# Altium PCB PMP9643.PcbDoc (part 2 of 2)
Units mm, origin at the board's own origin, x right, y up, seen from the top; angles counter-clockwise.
Board outline 136 x 91.5 mm, 2 copper layers (Top Layer, Bottom Layer), stack 1.575 mm thick; 90 components, 34 nets, 184 pads, 0 vias.
Unrouted connection lines stored in the file: 5.
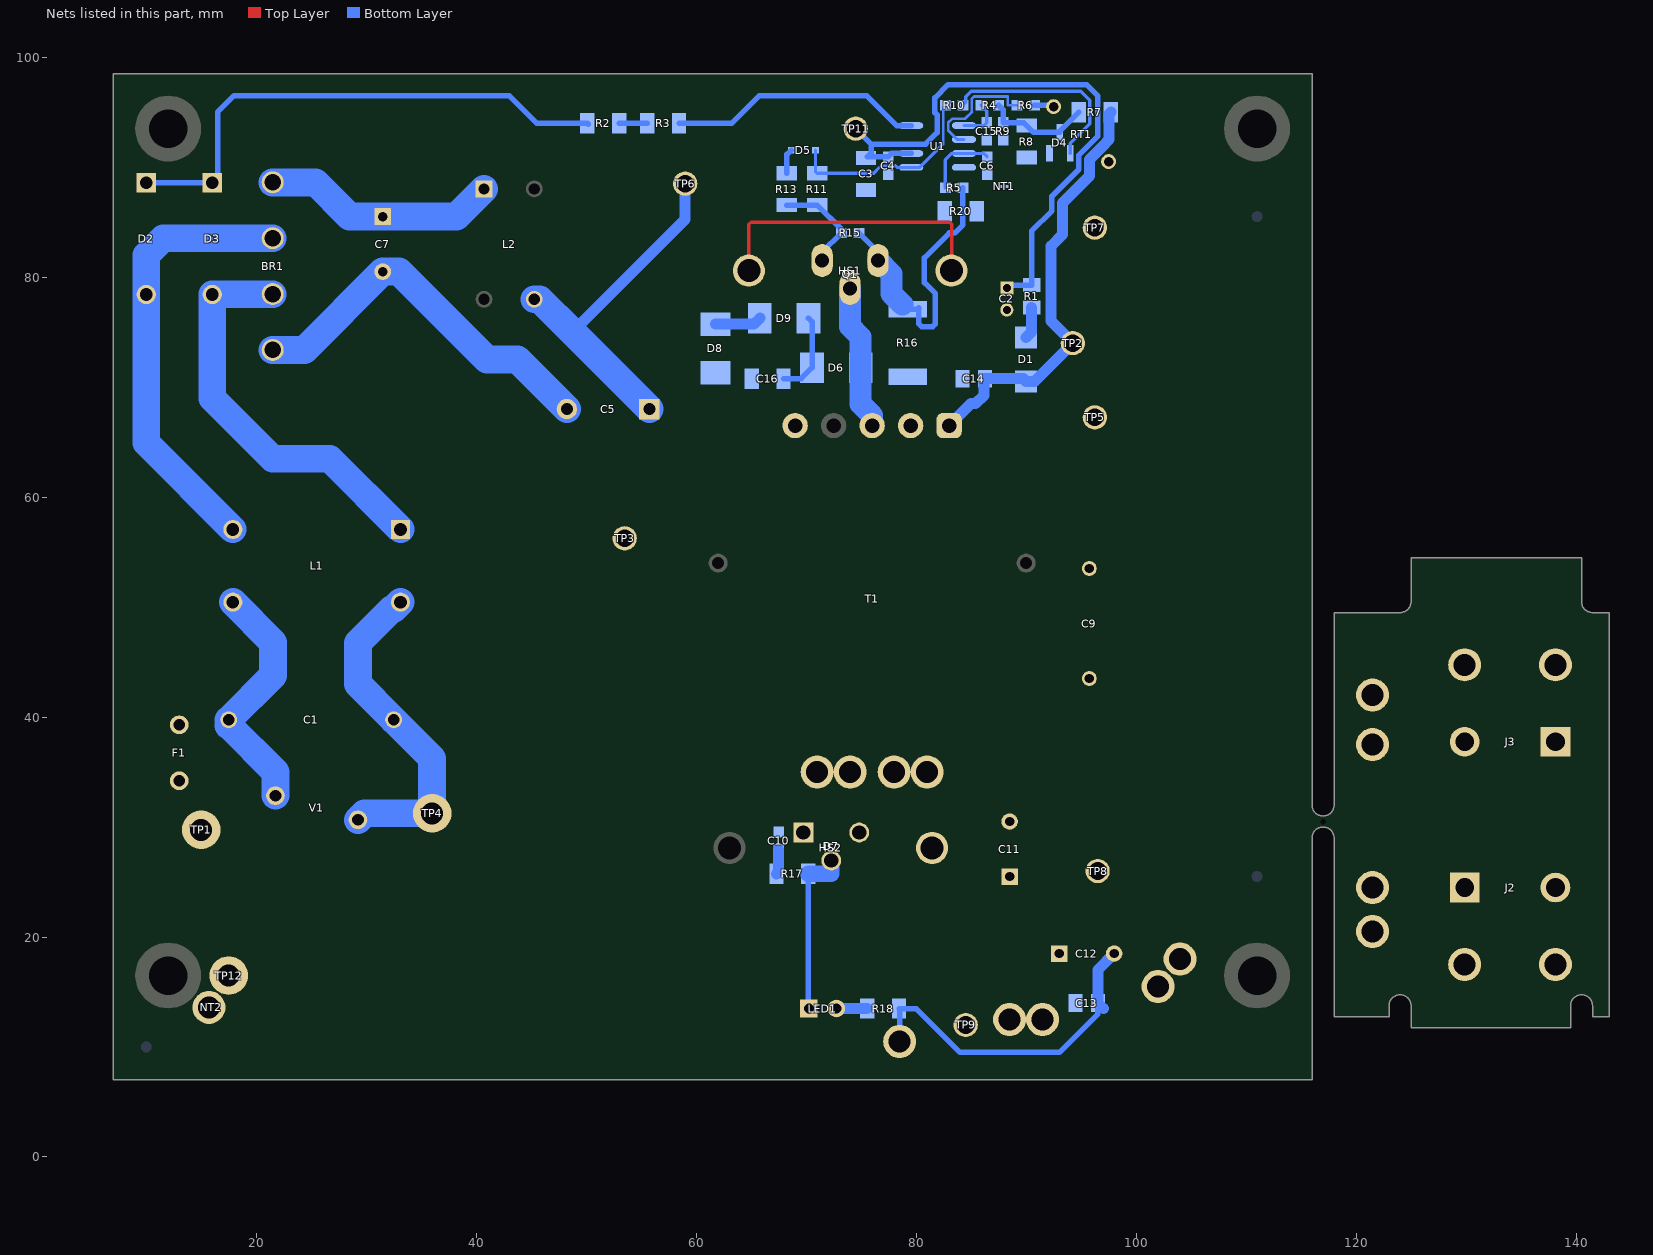
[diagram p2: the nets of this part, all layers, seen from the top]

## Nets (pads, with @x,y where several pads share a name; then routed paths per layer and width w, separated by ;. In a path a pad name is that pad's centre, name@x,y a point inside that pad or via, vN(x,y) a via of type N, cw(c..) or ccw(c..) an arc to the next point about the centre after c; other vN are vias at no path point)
+VOUT: C11.1 C12.1 C13.2 D7.2 HS2.2 J3.1 J3.2 LED1.1 pad.0@88.5,12.5 pad.0@91.5,12.5 pad.0@121.5,37.5 pad.0@121.5,42 pad.0@129.872,44.75 pad.0@138.127,44.75 R17.1 TP9.1 | length 15.6
  Bottom Layer w0.5: R17.1@70.2,25.75 70.2,13.55 LED1.1@70.25,13.5
  Bottom Layer w1.5: R17.1@70.2,25.75 72.29,25.75 D7.2@72.29,26.96
+VSW: D6.2 Q1.2 T1.3 | length 13.3
  Bottom Layer w2: Q1.2@74,78.97 74,75.5 74.96,74.54 D6.2@74.96,71.76 74.96,68.46 76,67.42 T1.3@76,66.5
-VPRI: BR1.4 C2.2 C5.2 C7.2 C9.2 C14.2 HS1.1 HS1.2 NT1.2 R16.1 RT1.1 T1.2 TP3.1 TP5.1 TP7.1 | length 62
  Top Layer w0.3: HS1.1@64.793,80.588 64.793,84.793 65,85 83.075,85 83.25,84.825 83.25,80.631 HS1.2@83.208,80.588
  Bottom Layer w2.54: BR1.4@21.5,73.38 24.38,73.38 C7.2@31.5,80.5 33,80.5 41,72.5 43.75,72.5 C5.2@48.25,68
ACA: BR1.2 D2.2 L1.2 | length 40.3
  Bottom Layer w2.5: L1.2@17.88,57.052 10,64.932 D2.2@10,78.42 10,82 11.54,83.54 BR1.2@21.5,83.54
ACB: BR1.3 D3.2 L1.1 | length 37
  Bottom Layer w2.5: BR1.3@21.5,78.46 21.46,78.42 D3.2@16,78.42 16,69 21.5,63.5 26.672,63.5 L1.1@33.12,57.052
CS: Q1.3 R5.1 R15.1 R16.2 | length 27.6
  Bottom Layer w0.5: R15.1@74.8,84.01 76.54,82.27 Q1.3@76.54,81.51 ; R16.2@78.75,77.5 78.81,77.5 R16.2@79.25,77.06 80.075,77.06 80.25,77.235 80.25,75.75 80.5,75.5 81.5,75.5 81.75,75.75 81.75,78.5 80.75,79.5 80.75,81.75 83.017,84.017 83.525,84.017 84.25,84.742 R5.1@84.25,88.125
  Bottom Layer w2: Q1.3@76.54,81.51 77.75,80.3 77.75,78.5 R16.2@78.75,77.5
DRV: D5.1 R10.2 R11.2 U1.5 | length 19.5
  Bottom Layer w0.2: 76.625,89.93 76.656,89.93 76.851,90.125 78.12,90.125 ; 82.45,94.375 82.45,95.425 82.475,95.45 R10.2@82.65,95.625
  Bottom Layer w0.25: 82.25,91.901 82.475,92.126 R10.2@82.475,95.45
  Bottom Layer w0.3: D5.1@70.85,91.55 70.85,89.6 R11.2@71,89.45 76.145,89.45 76.625,89.93 ; 78.12,90.125 78.275,89.97 U1.5@79.55,89.97 80.319,89.97 82.25,91.901
EARTH: NT2.1 pad.0@15.7,13.6 TP12.1
MAG: C14.1 D1.2 R7.1 T1.1 TP2.1 | length 39.5
  Bottom Layer w1: T1.1@83,66.5 85,68.5 85.41,68.5 86.16,69.25 86.16,70.654 C14.1@86.266,70.76 89.75,70.76 D1.2@90,70.51 90.76,70.51 TP2.1@94.25,74 92.25,76 92.25,82.806 93.3,83.856 93.3,86.75 95.755,89.205 95.755,90.7 96.93,91.875 97.55,92.495 97.55,94.85 R7.1@97.7,95
NetBR1_1: BR1.1 C7.1 L2.1 | length 21.5
  Bottom Layer w2.54: BR1.1@21.5,88.62 25.38,88.62 28.5,85.5 C7.1@31.5,85.5 38.198,85.5 L2.1@40.714,88.017
NetC1_1: C1.1 L1.4 TP4.1 V1.2 | length 30.7
  Bottom Layer w2.54: V1.2@29.25,30.65 29.85,31.25 TP4.1@36,31.25 36,36.25 C1.1@32.5,39.75 29.25,43 29.25,46.75 32.328,49.828 32.5,49.828 L1.4@33.12,50.448
NetC1_2: C1.2 F1.1 L1.3 V1.1 | length 22
  Bottom Layer w2.54: C1.2@17.5,39.25 21.75,35 V1.1@21.75,32.85 ; C1.2@17.5,39.75 21.539,43.789 21.539,46.789 L1.3@17.88,50.448
NetC6_1: C6.1 R5.2 U1.3 | length 6.7
  Bottom Layer w0.3: R5.2@82.65,88.125 82.65,90.65 83.24,91.24 U1.3@84.35,91.24 86.135,91.24 C6.1@86.45,90.925
NetC10_1: C10.1 R17.2 | length 2.3
  Bottom Layer w1: R17.2@67.3,25.75 67.5,25.95 C10.1@67.5,27.95
NetC15_2: C15.2 R4.2 U1.1 | length 4
  Bottom Layer w0.3: U1.1@84.35,93.78 86.155,93.78 C15.2@86.425,94.05 86.425,95.1 R4.2@85.9,95.625
NetC16_1: C16.1 D6.1 D9.1 | length 7.6
  Bottom Layer w0.5: C16.1@67.95,70.76 69.54,70.76 D6.1@70.54,71.76 70.54,75.93 D9.1@70.21,76.26
NetD1_1: D1.1 R1.2 | length 2.9
  Bottom Layer w1: D1.1@90,74.51 90.5,75.01 R1.2@90.5,77.244
NetD2_1: D2.1 D3.1 R2.2 | length 48
  Bottom Layer w0.5: D2.1@10,88.58 D3.1@16,88.58 16.5,89.08 16.5,95 18,96.5 43,96.5 45.5,94 R2.2@50.1,94 R2.2@50.2,93.9
NetD4_1: D4.1 R10.1 | length 18.3
  Bottom Layer w0.3: R10.1@84.25,95.625 84.5,95.875 84.5,96.4 85,96.9 94.97,96.9 95.8,96.07 95.8,93.93 94.025,92.155 D4.1@94.025,91.25
NetD4_3: D4.3 R4.1 R7.2 R8.2 R9.2 | length 9.8
  Bottom Layer w0.5: R4.1@87.5,95.625 87.925,95.2 R9.2@87.925,94.05 89.775,94.05 R8.2@90.05,93.775 90.675,93.15 D4.3@93.075,93.15 93.075,93.275 R7.2@94.8,95
NetD5_2: D5.2 R13.2 | length 2.3
  Bottom Layer w0.5: R13.2@68.25,89.45 68.25,91.15 D5.2@68.65,91.55
NetD8_1: D8.1 D9.2 | length 4.3
  Bottom Layer w1: D8.1@61.75,75.72 65.25,75.72 D9.2@65.79,76.26
NetF1_2: F1.2 TP1.1
NetLED1_2: LED1.2 R18.2 | length 2.8
  Bottom Layer w1: LED1.2@72.75,13.5 R18.2@75.55,13.5
NetQ1_1: Q1.1 R11.1 R13.1 R15.2 | length 9.4
  Bottom Layer w0.5: R13.1@68.25,86.55 R11.1@71,86.55 73.2,84.35 R15.2@73.2,84.01 71.46,82.27 Q1.1@71.46,81.51
NetR2_1: R2.1 R3.2 | length 2.5
  Bottom Layer w0.5: R2.1@53,94 R3.2@55.55,94
NetR3_1: R3.1 U1.8 | length 23.3
  Bottom Layer w0.5: R3.1@58.45,94 63.25,94 65.75,96.5 75.5,96.5 78.22,93.78 U1.8@79.55,93.78
NetR6_1: R6.1 U1.2 | length 11.3
  Bottom Layer w0.2: 84.966,94.942 85.05,95.026 85.05,96.21 85.075,96.235
  Bottom Layer w0.25: U1.2@84.35,92.51 83.74,92.51 82.925,93.325 82.925,94.039 83.291,94.405 84.465,94.405 85.075,95.015 ; 85.075,96.235 85.265,96.425 88.325,96.425 88.325,95.625 R6.1@89.15,95.625
NetR6_2: R6.2 RT1.2 | length 1.6
  Bottom Layer w0.5: R6.2@90.75,95.625 RT1.2@92.375,95.625
RET: C9.1 C11.2 C12.2 C13.1 J2.1 J2.2 NT2.2 pad.0@78.5,10.5 pad.0@102,15.5 pad.0@104,18 pad.0@121.5,20.5 pad.0@121.5,24.5 pad.0@129.872,17.5 pad.0@138.127,17.5 R18.1 T1.8 T1.9 TP8.1 | length 31
  Bottom Layer w0.5: pad.0@78.5,10.5 78.5,13.45 R18.1@78.45,13.5 80,13.5 84,9.5 93.032,9.5 96.516,12.984 C13.1@96.516,14
  Bottom Layer w1: C13.1@97.016,13.5 C13.1@96.516,14 96.516,17.016 C12.2@98,18.5
STARPT: C3.2 C4.2 C6.2 C15.1 D4.2 NT1.1 R8.1 R9.1 R20.1 R20.2 U1.4
VDC: C5.1 C16.2 D8.2 L2.3 T1.5 TP6.1 | length 32.3
  Bottom Layer w1: 48.75,75 59,85.25 TP6.1@59,88.5
  Bottom Layer w2.54: L2.3@45.286,77.984 45.766,77.984 48.75,75 C5.1@55.75,68
VDD: C2.1 C3.1 C4.1 R1.1 TP11.1 U1.6 | length 54.9
  Bottom Layer w0.5: TP11.1@74.5,93.5 75.9,92.1 ; U1.6@79.55,91.24 77.765,91.24 C4.1@77.45,90.925 75.55,90.925 75.9,91.275 75.9,92.1 ; C2.1@88.25,79.01 88.516,79.276 R1.1@90.5,79.276 90.5,84.175 92.35,86.025 92.35,87.35 94.805,89.805 94.805,91.093 96.537,92.825 96.537,96.461 95.498,97.5 82.914,97.5 81.7,96.286 81.7,94.964 81.9,94.764 81.9,93.138 80.862,92.1 75.9,92.1
VSEC: C10.2 D7.1 D7.3 T1.6 T1.7
pads on no net: FID1.1 FID2.1 FID3.1 H1.0 H2.0 H3.0 H4.0 H5.0 H6.0 H7.0 H8.0 HS2.1 L2.2 L2.4 T1.4 T1.MH1 T1.MH2

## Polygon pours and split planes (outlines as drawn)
STARPT on Bottom Layer "Bottom Layer-No Net" (solid, remove dead copper, pour order 2): 83.625,90.325 83.875,90.575 85.344,90.575 85.757,90.989 85.757,92.882 85.95,93.075 91.7,93.075 92.4,92.4 92.4,90.7 92.25,90.5 92,90.25 89,90.25 88,89.25 88,87 86.2,85.325 85.25,85.325 84.875,85.7 84.875,88.875 84.625,89.125 83.825,89.125 83.625,89.325

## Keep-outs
Keep-Out Layer:
  lines w0.25: 3.5,16.5 3.5,4.5 21.5,4.5 ; 41.5,4.5 120.5,4.5 120.5,6 ; 119,6 5,6 5,100.4 119,100.4
  text ".Layer_Name" at -1.744,-51.906 h1.52

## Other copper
Top Layer:
  text ".Layer_Name" at -1.744,-51.906 h1.52
Bottom Layer:
  region net -VPRI: 88.875,86.5 88.875,88.75 87,88.75 87,86.5
  region net ACB: 34.1,57.6 32.1,57.6 32.1,55.9 34.1,55.9
  region net NetC1_1: 34.1,51.65 32.1,51.65 32.1,49.8 34.1,49.8
  region net ACA: 18.8,57.2 16.8,57.2 16.8,55.1 18.8,55.1
  region net NetC1_2: 18.8,52.3 17.1,52.3 17.1,50.448 18.8,50.448
  region net +VOUT: 119.5,37 121.5,35 138,35 139.5,36.5 139.5,45.5 138,47 121.5,47 119.5,45
  region net RET: 119.5,19 123,15.5 138.5,15.5 139.5,16.5 139.5,26 138,27.5 121,27.5 119.5,26
  region net EARTH: 8.5,19.5 8.5,14 9.5,13 16.5,13 19,15.5 19,18.25 17.75,19.5
  region net +VOUT: 84,14 86,15.5 90.5,15.5 91,16 91,16.5 90.5,17 88,17 83.567,23.649 84.917,28.083 95,18 95,13.275 94.972,13.275 92.444,11 84.5,11 84,11.5
  region net RET: 77,35.5 77.085,33.425 79.51,31 87,31 90.5,27.5 90.5,24 95.75,18.75 95.75,12 103.25,12 105.5,14.25 105.5,34.01 95.76,43.75 93.24,43.75 87.5,38 78.5,38
  region net +VOUT: 71.5,27.085 72.25,27.75 76,27.75 77.26,29.01 86.74,29.01 89.25,26.5 89.25,22.75 72.75,22.75 71.5,24
  region net VSEC: 75.5,35 74,36.5 67,36.5 66.5,36 66.5,29.5 66.99,29.01 75.01,29.01 75.5,29.5
  region net STARPT: 74.875,88.575 75.976,88.575 76.976,89.574 78.176,89.574 78.625,89.125 81.075,89.125 81.625,88.575 81.625,87.325 82.125,86.825 83.125,86.825 83,85.351 83,85.25 80.5,85.25 79.875,85.825 78.375,87.325 75.225,87.325 74.875,87.675
  region net -VPRI: 78.75,73.76 79.75,74.76 81.75,74.76 82.5,75.51 82.5,81.5 85.5,84.5 86.5,84.5 88.25,86.25 88.25,88.75 89.5,88.75 90,88.25 90,85.25 87,82.25 87,78.26 86.25,77.51 86.25,75.26 83.5,72.51 80.25,72.51 79.75,72.01 79.75,71.547 78.75,71.547
  region net -VPRI: 87,77.01 87.5,77.51 88.25,77.51 88.75,77.01 88.75,74.078 86.72,72.048 85.312,72.048 84,70.735 80.75,67.5 80.75,65.25 81.5,64.5 84.5,64.5 86,66 92.25,66.01 95.75,69.51 95.75,76.26 94,77.75 94.25,85.75 96.75,88.25 96.75,90.25 97.25,90.75 97.75,90.75 98.75,89.75 98.75,65.76 91,58.01 56.99,58.01 48,67 47.75,66.75 47.75,66.25 56.49,57.51 93.75,57.51 96.25,55.01 96.25,53.01 93,53.01 90.75,55.26 89.25,55.26 87.25,53.26 64.75,53.26 62.75,55.26 61.25,55.26 59.25,53.26 53.5,53.26 45,62 45,68.25 38.25,75 44.5,75 56.99,62.51 78.25,62.51 78.9,63.16 78.9,69.5 78.39,70.01 77.75,70.01 77.75,71.355 78.171,71.776 83.606,71.776 87,75.17
  region net VDC: 58.75,72.51 66.25,72.51 66.25,72.5 66.5,72.205 66.5,69 66.75,68.5 68.25,68.5 69.25,67.5 69.25,66 56,66 55,67 54.5,71 57.24,71
  region net ACA: 17.8,53.85 18.8,54.85 18.8,55.85 16.8,55.85 16.8,54.85
  region net NetC1_2: 17.8,53.6 18.8,52.6 18.8,51.6 16.8,51.6 16.8,52.6
  region net NetC1_1: 33.1,53.65 34.1,52.65 34.1,51.65 32.1,51.65 32.1,52.65
  region net ACB: 33.1,53.9 34.1,54.9 34.1,55.9 32.1,55.9 32.1,54.9
  region net NetC1_2: 16.8,52.1 16.8,50.2 17.25,49.75 18.102,49.75 18.8,50.448 18.8,52.1
  region net NetC1_2: 17.5,38.5 18.25,39.25 18.25,40.5 17.5,41.25 13.25,41.25 12.25,40.25 12.25,39 12.75,38.5
  region net NetF1_2: 12.25,34.25 12.25,30.468 14.218,28.5 15.5,28.5 16.5,29.5 16.5,31.75 13.25,35
  region net NetD8_1: 60.5,76.75 61.25,77.5 66.75,77.5 66.75,75 66.5,74.75 60.5,74.75
  region net NetC16_1: 69.25,77.5 69.25,72.25 68.5,71.5 68.5,70.75 71.5,70.75 71.5,77 71,77.5
  text ".Layer_Name" at -1.744,-51.906 h1.52

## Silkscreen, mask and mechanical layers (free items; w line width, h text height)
Top Overlay:
  lines w0.2: 102.5,8.5 103.5,8.5 103.5,13.5 102.5,13.5 102.5,8.5 ; 110.5,8.5 111.5,8.5 111.5,13.5 110.5,13.5 110.5,8.5
  lines w0.25: 21.5,4.5 21.5,6 ; 41.5,4.5 41.5,6 ; 98,8.5 112.5,8.5 ; 98,8.5 98,10 ; 98,8.5 91.5,8.5 91.5,10 98,10 ; 98,10 112.5,10 ; 112.5,8.5 112.5,10 ; 112.5,8.5 116,8.5 116,10 112.5,10 ; 21.5,-4.25 41.5,-4.25 41.5,25.5 21.5,25.5 21.5,-4.25
  text "65W FLYBACK" at 47,95.25 h2
  text "VDD" at 77.25,93.25 h1.52
  text "VBULK" at 49.75,87.75 h1.52
  text "GND" at 99,81.25 h1.52
  text "MAG" at 97,72.5 h1.52
  text "GND" at 99.5,64.75 h1.52
  text "GND" at 46,55.5 h1.52
  text "+VOUT" at 118,44 h1.5
  text "FUSE 3.15A 250V" at 9.25,41.25 h1.5 r90
  text "B" at 78.5,37 h1.5
  text "A" at 71.75,36.75 h1.5
  text "DC OUTPUT" at 99.35,31.9 h1.5
  text "NEUTRAL" at 38.75,30.25 h1.52
  text "18.5V - 20.5V" at 99.15,29.7 h1.5
  text "7A MAX." at 99.1,27.4 h1.5
  text "LINE" at 7.75,26.75 h1.52
  text "RTN" at 101.5,20 h1.52
  text "EARTH" at 13.75,19.75 h1.52
  text "AC INPUT" at 42.775,17.65 h1.5
  text "RTN" at 119,15.5 h2
  text "88VAC TO 265VAC" at 42.775,15.25 h1.5
  text "2A MAX." at 42.775,13.15 h1.5
  text "RTN" at 76.4,12.69 h1.52
  text "FRONT PANEL" at 61.5,8 h1.5
  text "+VOUT" at 81.3,7.7 h2
  text ".Layer_Name" at -1.744,-51.906 h1.52
Bottom Overlay:
  drawing of 2707 lines, arcs and shapes, not listed
  text "AC INPUT" at 34.75,46.25 h1.5
  text "88VAC TO 265VAC" at 34.75,43.75 h1.5
  text "2A MAX." at 34.75,41.25 h1.4
  text "65W FLYBACK" at 61,40 h2
  text "DC OUTPUT" at 111.92,30.85 h1.5
  text "+19.5V 3.34A" at 113.92,28.6 h1.5
  text "RTN" at 105,20 h2
  text "+VOUT" at 92,14.5 h2
  text ".PCB_Rev" at 42.5,8 h1.52
  text ".PRJ_Number" at 55,8 h1.52
  text ".Layer_Name" at -1.744,-51.906 h1.52
Top Paste:
  text ".Layer_Name" at -1.744,-51.906 h1.52
Bottom Paste:
  text ".Layer_Name" at -1.744,-51.906 h1.52
Top Solder:
  text ".Layer_Name" at -1.744,-51.906 h1.52
  text ".Layer_Name" at -1.744,-51.906 h1.52
Bottom Solder:
  rectangle: 17.6,51.7 18,55.8
  rectangle: 32.86,51.75 33.26,55.85
  text ".Layer_Name" at -1.744,-51.906 h1.52
Drill Guide:
  text ".Layer_Name" at -1.744,-51.906 h1.52
M1 Board Outline:
  lines w0.25: 116,29 cw(c117,29) 117,30 cw(c117,29) 118,29 118,12.75 118.5,12.75 123,12.75 123,13.75 cw(c124,13.75) 124,14.75 cw(c124,13.75) 125,13.75 125,11.75 139.5,11.75 139.5,12.75 139.5,13.75 cw(c140.5,13.75) 140.5,14.75 cw(c140.5,13.75) 141.5,13.75 141.5,12.75 143,12.75 ; 116,32 ccw(c117,32) 117,31 ccw(c117,32) 118,32 118,49.5 118.5,49.5 124,49.5 ccw(c124,50.5) 125,50.5 125,54.5 140.5,54.5 140.5,50.5 ccw(c141.5,50.5) 141.5,49.5 143,49.5 ; 96.95,9.3 cw(c97.95,9.3) 97.95,10.3 112.55,10.3 cw(c112.55,9.3) 113.55,9.3 cw(c112.55,9.3) 112.55,8.3 97.95,8.3 cw(c97.95,9.3) 96.95,9.3
  lines w0.254: 116,29 116,7 110.25,7 85.5,7 7,7 7,11.5 7,98.5 116,98.5 116,84.375 116,76.125 116,32 ; 143,12.75 143,49.5
  text ".Layer_Name" at -1.744,-51.906 h1.52
M2 Board Dimensions:
  rectangle: -16.412,-37.352 -13.237,-34.177
  rectangle: -13.237,-40.527 -3.712,-37.352
  lines w0.178: -16.412,-37.352 8.988,-37.352 ; -13.237,-40.527 -13.237,-34.177 ; -10.062,-40.527 -10.062,-34.177 ; -3.712,-40.527 -3.712,-34.177 ; 2.638,-40.527 2.638,-34.177 ; -16.412,-40.527 8.988,-40.527 8.988,-34.177 -16.412,-34.177 -16.412,-40.527
  lines w0.2: 7,52.5 ccw(c6,52.5) 5,52.5 5,6 ccw(c6,6) 6,5 60,5 ccw(c60,6) 60,7 ; 7,55.5 cw(c6,55.5) 5,55.5 5,99.5 cw(c6,99.5) 6,100.5 60,100.5 cw(c60,99.5) 60,98.5 ; 63,7 ccw(c63,6) 63,5 117,5 ccw(c117,6) 118,6 118,7.5 118,9.75 131,9.75 ccw(c131,10.75) 131,11.75 ; 63,98.5 cw(c63,99.5) 63,100.5 117,100.5 cw(c117,99.5) 118,99.5 118,51.5 123,51.5 123,55.5 cw(c124,55.5) 124,56.5 131,56.5 cw(c131,55.5) 131,54.5 ; 134,11.75 ccw(c134,10.75) 134,9.75 144,9.75 ccw(c144,10.75) 145,10.75 145,29 ccw(c144,29) 143,29 ; 134,54.5 cw(c134,55.5) 134,56.5 141.5,56.5 cw(c141.5,55.5) 142.5,55.5 142.5,51.5 144,51.5 cw(c144,50.5) 145,50.5 145,32 cw(c144,32) 143,32 ; 0,0 0,105.5 150,105.5 150,0 0,0
  lines w0.254: -16.412,-42.178 -16.412,-41.67 ; -14.888,-42.432 -16.412,-41.924 ; -14.888,-41.416 -16.412,-41.924 ; -10.213,-41.924 -16.412,-41.924 ; 2.788,-41.924 8.988,-41.924 ; 7.464,-42.432 8.988,-41.924 ; 7.464,-41.416 8.988,-41.924 ; 8.988,-42.178 8.988,-41.67
  text "25.4 (mm)" at -9.959,-42.838 h1.52
  text ".Layer_Name" at -1.744,-51.906 h1.52
M3 3D STEP Top:
  text ".Layer_Name" at -1.744,-51.906 h1.52
M4 3D STEP Bottom:
  text ".Layer_Name" at -1.744,-51.906 h1.52
M5 Assembly Top:
  lines w0.254: -23.817,-53.726 143.823,-53.726 ; -23.817,-48.562 143.874,-48.562 ; -23.817,-43.397 -23.817,-58.891 77.91,-58.891 143.874,-58.891 143.874,-43.397 -23.804,-43.397 -23.804,-58.891 16.214,-58.891 ; 38.794,-58.891 38.794,-43.397 ; 70.976,-48.562 70.976,-43.397 ; 92.312,-48.562 92.312,-43.397 ; 108.111,-59.056 108.111,-53.904
  text "LED IS MOUNTED IN ENCLOSURE" at 64.5,1.5 h1.5
  text "COMPONENTS MARKED 'DNP' SHOULD NOT BE POPULATED." at 12.899,-38.19 h1.52
  text "ASSEMBLY VARIANT:" at 12.886,-41.124 h1.52
  text ".VariantName" at 39.201,-41.124 h1.52
  text "PCB VIEWED FROM TOP SIDE" at -22.204,-46.754 h1.52
  text "BOARD #:" at 40.699,-46.754 h1.52
  text ".PRJ_Number" at 54.555,-46.754 h1.52
  text "REV:" at 76.005,-46.754 h1.52
  text ".PCB_Rev" at 83.41,-46.754 h1.52
  text "SVN REV:" at 97.291,-46.754 h1.52
  text ".VersionControl_RevNumber" at 110.143,-46.754 h1.52
  text "IGNORE ->" at -22.204,-51.906 h1.52
  text "PLOT NAME =" at -22.204,-57.134 h1.52
  text ".plot_File_Name" at -1.744,-57.134 h1.52
  text "GENERATED    :" at 40.75,-57.134 h1.52
  text ".Print_Date" at 62.836,-57.134 h1.52
  text ".Print_Time" at 81.352,-57.134 h1.52
  text "TEXAS INSTRUMENTS" at 113.47,-57.134 h1.52
M6 Assembly Bottom:
  lines w0.254: -23.829,-48.574 143.862,-48.574 ; -23.778,-53.739 143.862,-53.739 ; 11.934,-59.069 11.934,-53.917 ; 27.733,-48.574 27.733,-43.41 ; 49.069,-48.574 49.069,-43.41 ; 81.251,-58.904 81.251,-43.41 ; 103.831,-58.904 143.849,-58.904 143.849,-43.41 -23.829,-43.41 -23.829,-58.904 42.135,-58.904 143.862,-58.904 143.862,-43.41
  text "COMPONENTS MARKED 'DNP' SHOULD NOT BE POPULATED." at 138.591,-38.177 h1.52
  text ".VariantName" at 112.073,-41.124 h1.52
  text "ASSEMBLY VARIANT:" at 138.464,-41.124 h1.52
  text ".VersionControl_RevNumber" at 9.902,-46.767 h1.52
  text "SVN REV:" at 22.754,-46.767 h1.52
  text ".PCB_Rev" at 36.635,-46.767 h1.52
  text "REV:" at 44.04,-46.767 h1.52
  text ".PRJ_Number" at 65.49,-46.767 h1.52
  text "BOARD #:" at 79.346,-46.767 h1.52
  text "PCB VIEWED FROM BOTTOM SIDE" at 142.249,-46.767 h1.52
  text "IGNORE ->" at 48.316,-51.906 h1.52
  text "TEXAS INSTRUMENTS" at 6.575,-57.147 h1.52
  text ".Print_Time" at 38.693,-57.147 h1.52
  text ".Print_Date" at 57.209,-57.147 h1.52
  text "GENERATED    :" at 79.295,-57.147 h1.52
  text ".plot_File_Name" at 121.789,-57.147 h1.52
  text "PLOT NAME =" at 142.249,-57.147 h1.52
M9 Title Sheet:
  drawing of 57 lines, arcs and shapes, not listed
  text "1" at 2.392,174.027 h1.78
  text "2" at 65.782,174.027 h1.78
  text "3" at 129.011,174.027 h1.78
  text "4" at 192.681,174.027 h1.78
  text "5" at 256.155,174.027 h1.78
  text "6" at 319.782,174.027 h1.78
  text "A" at -26.979,144.995 h1.78
  text "A" at 348.941,144.995 h1.78
  text "B" at -26.979,84.543 h1.78
  text "B" at 348.941,84.543 h1.78
  text "C" at -26.979,24.218 h1.78
  text "C" at 348.941,24.218 h1.78
  text "PROJECT TITLE:" at 271.725,-23.052 h1.14
  text ".PRJ_Title" at 272.995,-26.438 h1.78
  text "DESIGNED FOR:" at 271.725,-30.697 h1.14
  text ".PRJ_Customer" at 272.995,-34.253 h1.78
  text "D" at -26.979,-35.98 h1.78
  text "D" at 348.941,-35.98 h1.78
  text "FILE NAME:" at 271.725,-38.317 h1.14
  text ".PCB_File_Name_No_Path" at 272.995,-41.365 h1.78
  text "Texas Instruments (TI) and/or its licensors do not warrant the accuracy or completeness of this specification" at 145.5,-45.476 h1.14
  text "ENGINEER:" at 271.725,-45.683 h1.14
  text "LAYOUT BY:" at 309.952,-45.683 h1.14
  text "or any information contained therein. TI and/or its licensors do not warrant that this design will meet" at 144.357,-48.337 h1.14
  text ".PRJ_Engineer" at 272.995,-49.62 h1.78
  text ".PCB_Layout" at 311.235,-49.62 h1.78
  text "the specifications, will be suitable for your application or fit for any particular purpose, or will operate in" at 144.357,-51.199 h1.14
  text ".Layer_Name" at -1.744,-51.906 h1.52
  text "ALTIUM DESIGNER VERSION:" at 309.952,-53.557 h1.14
  text "an implementation. TI and/or its licensors do not warrant that the design is production worthy. You should" at 144.357,-54.061 h1.14
  text "completely validate and test your design implementation to confirm the system functionality for your application." at 145.5,-56.923 h1.14
  text ".print_Scale" at 272.995,-56.944 h1.78
  text ".Application_BuildNumber" at 311.235,-56.944 h1.78
  text "1" at 2.392,-62.193 h1.78
  text "2" at 65.782,-62.193 h1.78
  text "3" at 129.011,-62.193 h1.78
  text "4" at 192.681,-62.193 h1.78
  text "5" at 256.155,-62.193 h1.78
  text "6" at 319.782,-62.193 h1.78
M10 Fab Notes:
  drawing of 210 lines, arcs and shapes, not listed
  text "DESIGN INFORMATION" at 298.078,142.874 h1.52
  text "(REFER TO ARRAY/PANEL PROFILING INFORMATION)" at 288.894,138.766 h1.52
  text "BOARD SIZE" at 271.47,138.657 h1.52
  text "Number of Layers :" at 281.706,130.402 h1.52
  text "2" at 309.514,130.148 h1.52
  text "MIN. TRACK WIDTH:" at 281.706,126.872 h1.52
  text "8" at 309.551,126.872 h1.52
  text "MIL" at 313.482,126.872 h1.52
  text "MIN. CLEARANCE:" at 281.706,123.519 h1.52
  text "8" at 309.551,123.519 h1.52
  text "MIL" at 313.482,123.519 h1.52
  text "MIN. VIA PAD SIZE:" at 281.706,120.166 h1.52
  text "16" at 308.789,120.166 h1.52
  text "MIL" at 313.482,120.166 h1.52
  text "0.05mm (2MIL)" at 299.359,116.567 h1.52
  text "MINIMUM ANNULAR RING" at 273.344,116.458 h1.52
  text "EXTERNAL" at 317.342,116.458 h1.52
  text "PER" at 278.424,113.461 h1.52
  text "IPC-D-275 CLASS 2 LEVEL C" at 284.012,113.461 h1.52
  text "MIL, HOLES" at 321.813,110.609 h1.52
  text "+/-" at 311.844,110.59 h1.52
  text "+/-" at 333.536,110.59 h1.52
  text "REGISTRATION TOLERANCES:" at 273.344,110.463 h1.52
  text "METAL" at 303.818,110.463 h1.52
  text "5" at 318.454,110.463 h1.52
  text "3" at 339.612,110.463 h1.52
  text "MIL" at 342.565,110.463 h1.52
  text "MATERIAL:" at 271.445,105.143 h1.52
  text "FR-4 High Tg" at 296.5,101.579 h1.52
  text "FR-408" at 282.138,101.361 h1.52
  text "X" at 292.603,101.361 h1.52
  text "OTHER" at 319.933,101.361 h1.52
  text "62 MIL (1.6mm) +/-10%" at 290.269,97.228 h1.52
  text "THICKNESS:" at 273.344,97.119 h1.52
  text "X" at 287.013,97.119 h1.52
  text "OTHER" at 322.905,97.119 h1.52
  text "TOLERANCE:" at 273.344,93.106 h1.52
  text "X" at 294.662,93.106 h1.52
  text "ANSI IPC-6012 TYPE 3 CLASS 2" at 299.41,93.106 h1.52
  text "OTHER +/-" at 299.41,89.144 h1.52
  text "BOW & TWIST:" at 273.344,85.156 h1.52
  text "X" at 294.662,85.156 h1.52
  text "ANSI IPC-6012 TYPE 3 CLASS 2" at 299.41,85.156 h1.52
  text "OTHER +/-" at 299.41,81.13 h1.52
  text "COPPER THICKNESS (FINISHED):" at 271.445,77.688 h1.52
  text "1.4MIL (1oz)" at 293.797,73.809 h1.52
  text "2MIL (1.4oz)" at 313.278,73.809 h1.52
  text "2.8MIL (2oz)" at 331.744,73.809 h1.52
  text "OUTER:" at 280.512,73.7 h1.52
  text "X" at 328.5,73.6 h1.52
  text "X" at 328.7,69.9 h1.52
  text "1.4MIL (1oz)" at 293.797,69.821 h1.52
  text "2.8MIL (2oz)" at 313.278,69.821 h1.52
  text "N/A" at 331.733,69.831 h1.52
  text "INNER SIGNAL:" at 273.17,69.713 h1.52
  text "DRILLING:" at 271.445,66.182 h1.52
  text "REFERENCE:" at 273.344,63.21 h1.52
  text "X" at 289.809,63.21 h1.52
  text "AS SHOWN" at 294.559,63.21 h1.52
  text "X" at 312.694,63.21 h1.52
  text "NC_DRILL FILES" at 316.174,63.21 h1.52
  text "PTH MIN COPPER THICKNESS:" at 273.344,59.197 h1.52
  text "X" at 307.64,59.197 h1.52
  text "1MIL" at 311.119,59.197 h1.52
  text "OTHER" at 323.743,59.197 h1.52
  text "BOARD FINISH:" at 271.445,55.158 h1.52
  text "SILKSCREEN:" at 275.387,52.161 h1.52
  text "X" at 299.486,52.161 h1.52
  text "TOP" at 302.687,52.161 h1.52
  text "X" at 312.44,52.161 h1.52
  text "BOTTOM" at 315.666,52.161 h1.52
  text "SILKSCREEN COLOR:" at 275.387,47.919 h1.52
  text "X" at 299.46,47.919 h1.52
  text "WHITE" at 302.687,47.919 h1.52
  text "OTHER" at 315.666,47.919 h1.52
  text "SOLDER RESIST COLOR:" at 275.387,43.601 h1.52
  text "X" at 289.808,39.558 h1.52
  text "GREEN" at 293.035,39.558 h1.52
  text "BLUE" at 308.046,39.558 h1.52
  text "OTHER" at 321.711,39.558 h1.52
  text "IMMERSION GOLD (ENIG)" at 298.394,34.769 h1.52
  text "ENEPIG" at 332.368,34.686 h1.52
  text "SURFACE FINISH:" at 271.445,34.661 h1.52
  text "Pb FREE HASL" at 325.774,30.873 h1.52
  text "X" at 311.5,30.8 h1.52
  text "IMM. TIN/SILVER OR EQUIV" at 279.815,30.673 h1.52
  text "OTHER" at 316.174,30.673 h1.52
  text "ARRAY/PANEL:" at 271.445,26.126 h1.52
  text "X" at 293.4,26 h1.52
  text "CUT AND TRIM PER MECH LAYER 1" at 298.394,26.017 h1.52
  text "N.C. ROUTE" at 298.394,22.164 h1.52
  text "V. SCORE" at 320.39,22.164 h1.52
  text "CERTIFICATION:" at 271.445,18.684 h1.52
  text "MATERIALS AND WORKMANSHIP FOR ALL PCBS" at 289.86,18.684 h1.52
  text "TO MEET OR EXCEED THE REQUIREMENTS OF:" at 289.86,16.195 h1.52
  text "X" at 280.373,12.728 h1.52
  text "ANSI IPC-A-600F CLASS ->" at 283.903,12.728 h1.52
  text "X" at 325.535,12.728 h1.52
  text "2" at 328.557,12.728 h1.52
  text "1" at 320.556,12.69 h1.52
  text "3" at 337.548,12.69 h1.52
  text "X" at 280.425,8.676 h1.52
  text "UL 94V-0" at 283.903,8.676 h1.52
  text "X" at 301.05,8.676 h1.52
  text "RoHS" at 304.528,8.676 h1.52
  text "OTHER" at 320.896,8.676 h1.52
  text "PER ORDER" at 330.981,8.676 h1.52
  text "ADDITIONAL REQUIREMENTS:" at 271.445,5.095 h1.52
  text "MICROSECTION:" at 273.344,2.174 h1.52
  text "YES" at 296.349,2.174 h1.52
  text "REQUIRED" at 318.231,-1.792 h1.52
  text "BARE BOARD ELEC. TEST:" at 273.344,-1.865 h1.52
  text "NONE" at 306.509,-1.865 h1.52
  text "X" at 315.006,-1.865 h1.52
  text "PER ORDER" at 333.268,-1.865 h1.52
  text "MANUFACTURER'S UL:" at 273.344,-5.852 h1.52
  text "RAIL" at 302.953,-5.961 h1.52
  text "METAL" at 315.445,-5.961 h1.52
  text "X" at 324.976,-5.97 h1.52
  text "SILK" at 328.442,-5.961 h1.52
  text ".Layer_Name" at -1.744,-51.906 h1.52
M11 Gerber Information:
  lines w0.254: -23.817,-53.726 143.823,-53.726 ; -23.817,-48.562 143.874,-48.562 ; -23.817,-43.397 -23.817,-58.891 77.91,-58.891 143.874,-58.891 143.874,-43.397 -23.804,-43.397 -23.804,-58.891 16.214,-58.891 ; 38.794,-58.891 38.794,-43.397 ; 70.976,-48.562 70.976,-43.397 ; 92.312,-48.562 92.312,-43.397 ; 108.111,-59.056 108.111,-53.904
  text "ALL ARTWORK VIEWED FROM TOP SIDE" at -22.204,-46.754 h1.52
  text "BOARD #:" at 40.699,-46.754 h1.52
  text ".PRJ_Number" at 54.555,-46.754 h1.52
  text "REV:" at 76.005,-46.754 h1.52
  text ".PCB_Rev" at 83.41,-46.754 h1.52
  text "SVN REV:" at 97.291,-46.754 h1.52
  text ".VersionControl_RevNumber" at 110.143,-46.754 h1.52
  text "LAYER NAME =" at -22.204,-51.906 h1.52
  text "PLOT NAME =" at -22.204,-57.134 h1.52
  text ".plot_File_Name" at -1.744,-57.134 h1.52
  text "GENERATED    :" at 40.75,-57.134 h1.52
  text ".Print_Date" at 62.836,-57.134 h1.52
  text ".Print_Time" at 81.352,-57.134 h1.52
  text "TEXAS INSTRUMENTS" at 113.47,-57.134 h1.52
M12 Stackup:
  text ".Layer_Name" at -1.744,-51.906 h1.52
M13 Component Bodies Top:
  text ".Layer_Name" at -1.744,-51.906 h1.52
M14 Component Bodies Bottom:
  text ".Layer_Name" at -1.744,-51.906 h1.52
M15 Courtyards Top:
  text ".Layer_Name" at -1.744,-51.906 h1.52
M16 Courtyards Bottom:
  text ".Layer_Name" at -1.744,-51.906 h1.52
Drill Drawing:
  text ".legend" at 161.612,60.928 h1.52
  text "Drill Table" at 161.5,57.5 h1.52
  text ".Layer_Name" at -1.744,-51.906 h1.52

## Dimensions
0,105.5 to 150,105.5 on M2 Board Dimensions
0,105.5 to 0,0 on M2 Board Dimensions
